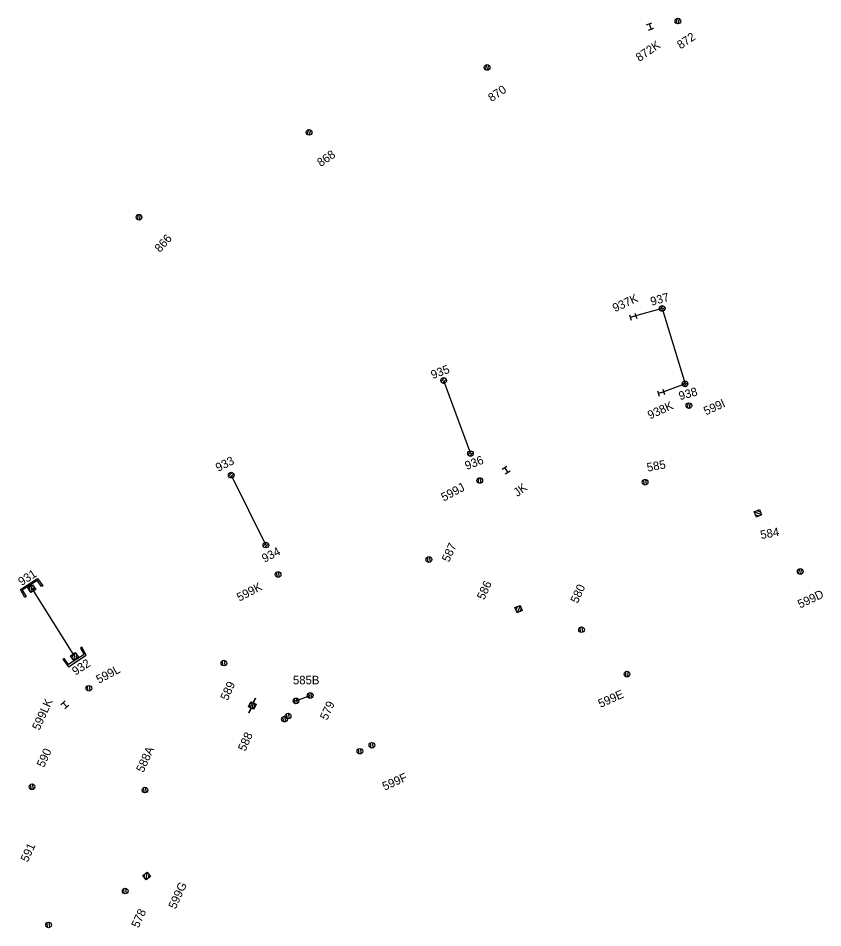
# Model space of a CAD drawing. Extents: x -595867 to -593796, y -1159595 to -1157495.
# Drawn here: x -594550.3 to -594408.1, y -1157774.7 to -1157614 of the extents above; entities that cross this region are included whole.
import ezdxf

# ---------------------------------------------------------------- set-up
doc = ezdxf.new("R2010")
doc.units = 0
for name, color, linetype in [('BVK_kanalizace_jednotna_nova', 7, 'Continuous'), ('SO31_06_54_1-protlak', 7, 'Continuous'), ('Teplarny Horkovod', 7, 'Continuous')]:
    doc.layers.add(name, color=color, linetype=linetype)

# ---------------------------------------------------------------- blocks, each defined once
blk = doc.blocks.new('C661_1')
at = {"layer": 'SO31_06_54_1-protlak'}
for p, q in [((-0.005, 0.0003), (-0.0003, 0.005)), ((-0.005, -0.005), (0.005, 0.005)), ((0.0003, -0.005), (0.005, -0.0003))]:
    blk.add_line(p, q, dxfattribs=at)
blk.add_lwpolyline([(-0.005, 0.005), (0.005, 0.005), (0.005, -0.005), (-0.005, -0.005)], close=True, dxfattribs=at)
blk.add_lwpolyline([(-0.005, 0.005), (0.005, 0.005), (0.005, -0.005), (-0.005, -0.005), (-0.005, 0.005)], dxfattribs=at)
blk = doc.blocks.new('C666')
at = {"layer": 'SO31_06_54_1-protlak'}
for p, q in [((-0.005, 0.0001), (-0.0001, 0.005)), ((-0.0048, -0.005), (0.005, 0.0048)), ((0.0049, 0), (0.015, 0)), ((-0.005, 0), (-0.015, 0)), ((0.0005, -0.005), (0.005, -0.0005))]:
    blk.add_line(p, q, dxfattribs=at)
blk.add_lwpolyline([(-0.005, 0.005), (0.005, 0.005), (0.005, -0.005), (-0.005, -0.005)], close=True, dxfattribs=at)
blk.add_lwpolyline([(-0.005, 0.005), (0.005, 0.005), (0.005, -0.005), (-0.005, -0.005), (-0.005, 0.005)], dxfattribs=at)
blk = doc.blocks.new('C661_3')
at = {"layer": 'Teplarny Horkovod'}
for p, q in [((-0.5, 0.03), (-0.03, 0.5)), ((-0.5, -0.5), (0.5, 0.5)), ((0.03, -0.5), (0.5, -0.03))]:
    blk.add_line(p, q, dxfattribs=at)
blk.add_lwpolyline([(-0.5, 0.5), (0.5, 0.5), (0.5, -0.5), (-0.5, -0.5)], close=True, dxfattribs=at)
blk.add_lwpolyline([(-0.5, 0.5), (0.5, 0.5), (0.5, -0.5), (-0.5, -0.5), (-0.5, 0.5)], dxfattribs=at)
blk = doc.blocks.new('C725')
at = {"layer": 'Teplarny Horkovod'}
for p, q in [((-0.46, -0.18), (0.18, 0.46)), ((-0.2, -0.45), (0.45, 0.2))]:
    blk.add_line(p, q, dxfattribs=at)
blk.add_circle((0, 0), 0.5, dxfattribs=at)
blk = doc.blocks.new('C662')
at = {"layer": 'Teplarny Horkovod'}
for p, q in [((-0.5, 0.5), (0.5, 0.5)), ((0, 0.5), (0, -0.5)), ((-0.5, -0.5), (0.5, -0.5))]:
    blk.add_line(p, q, dxfattribs=at)

msp = doc.modelspace()

# ---------------------------------------------------------------- linework, layer by layer
at = {"layer": 'BVK_kanalizace_jednotna_nova'}
for p, q in [((-594439.28, -1157615.19), (-594438.34, -1157614.83)), ((-594434.04, -1157614.89), (-594433.79, -1157614.02)), ((-594433.69, -1157615.01), (-594433.43, -1157614.11)), ((-594438.92, -1157616.13), (-594437.98, -1157615.77)), ((-594438.81, -1157615.01), (-594438.45, -1157615.95)), ((-594467.76, -1157623.08), (-594467.51, -1157622.21)), ((-594467.41, -1157623.2), (-594467.15, -1157622.3)), ((-594499.23, -1157634.55), (-594498.98, -1157633.68)), ((-594498.88, -1157634.67), (-594498.62, -1157633.77)), ((-594529.18, -1157649.61), (-594529.15, -1157648.7)), ((-594528.81, -1157649.63), (-594528.78, -1157648.7)), ((-594432.1, -1157682.82), (-594431.85, -1157681.95)), ((-594431.75, -1157682.94), (-594431.49, -1157682.04)), ((-594464.78, -1157693.65), (-594463.94, -1157693.11)), ((-594464.36, -1157693.38), (-594463.82, -1157694.22)), ((-594468.96, -1157696.11), (-594468.93, -1157695.2)), ((-594468.58, -1157696.13), (-594468.56, -1157695.2)), ((-594464.24, -1157694.49), (-594463.4, -1157693.95)), ((-594439.64, -1157696.45), (-594439.8, -1157695.55)), ((-594439.27, -1157696.39), (-594439.43, -1157695.48)), ((-594418.95, -1157701.73), (-594420.25, -1157701.21)), ((-594419.43, -1157701.94), (-594420.05, -1157701.7)), ((-594419.15, -1157701.25), (-594419.77, -1157701)), ((-594477.85, -1157710.11), (-594478.01, -1157709.21)), ((-594477.48, -1157710.05), (-594477.65, -1157709.14)), ((-594412.42, -1157712.12), (-594412.17, -1157711.25)), ((-594412.07, -1157712.24), (-594411.81, -1157711.34)), ((-594504.5, -1157712.76), (-594504.66, -1157711.86)), ((-594504.13, -1157712.71), (-594504.3, -1157711.79)), ((-594450.88, -1157722.49), (-594451.04, -1157721.59)), ((-594450.51, -1157722.44), (-594450.67, -1157721.52)), ((-594513.72, -1157728.32), (-594513.88, -1157727.41)), ((-594514.09, -1157728.38), (-594514.25, -1157727.48)), ((-594442.95, -1157730.3), (-594442.92, -1157729.39)), ((-594442.58, -1157730.32), (-594442.55, -1157729.39)), ((-594537.95, -1157732.84), (-594538.11, -1157731.94)), ((-594537.58, -1157732.78), (-594537.74, -1157731.87)), ((-594501.24, -1157734.58), (-594498.72, -1157733.63)), ((-594498.83, -1157734.11), (-594498.99, -1157733.21)), ((-594498.46, -1157734.05), (-594498.62, -1157733.14)), ((-594542.77, -1157735.27), (-594542.04, -1157734.58)), ((-594542.4, -1157734.93), (-594541.72, -1157735.65)), ((-594542.08, -1157736), (-594541.35, -1157735.31)), ((-594501.35, -1157735.06), (-594501.51, -1157734.16)), ((-594500.98, -1157735), (-594501.14, -1157734.09)), ((-594502.74, -1157737.74), (-594502.9, -1157736.84)), ((-594502.37, -1157737.69), (-594502.54, -1157736.77)), ((-594503.38, -1157738.28), (-594503.54, -1157737.38)), ((-594503.01, -1157738.23), (-594503.18, -1157737.31)), ((-594490.05, -1157743.97), (-594490.21, -1157743.07)), ((-594489.68, -1157743.91), (-594489.84, -1157743)), ((-594487.92, -1157742.91), (-594488.08, -1157742.01)), ((-594487.55, -1157742.85), (-594487.71, -1157741.94)), ((-594547.99, -1157750.23), (-594548.15, -1157749.33)), ((-594547.62, -1157750.18), (-594547.79, -1157749.26)), ((-594528.03, -1157750.81), (-594528.19, -1157749.91)), ((-594527.66, -1157750.75), (-594527.82, -1157749.84)), ((-594528.04, -1157765.78), (-594527.95, -1157765.13)), ((-594527.72, -1157766.21), (-594527.53, -1157764.81)), ((-594527.3, -1157765.89), (-594527.21, -1157765.23)), ((-594531.53, -1157768.64), (-594531.69, -1157767.74)), ((-594531.16, -1157768.58), (-594531.32, -1157767.67)), ((-594545.08, -1157774.64), (-594545.24, -1157773.74)), ((-594544.71, -1157774.58), (-594544.87, -1157773.67))]:
    msp.add_line(p, q, dxfattribs=at)
for points in [[(-594419.86, -1157702.13), (-594420.26, -1157701.21), (-594419.34, -1157700.81), (-594418.94, -1157701.73)], [(-594528.32, -1157765.41), (-594527.53, -1157764.81), (-594526.92, -1157765.6), (-594527.72, -1157766.21)]]:
    msp.add_lwpolyline(points, close=True, dxfattribs=at)
for points in [[(-594419.86, -1157702.13), (-594420.26, -1157701.21), (-594419.34, -1157700.81), (-594418.94, -1157701.73), (-594419.86, -1157702.13)], [(-594528.32, -1157765.41), (-594527.53, -1157764.81), (-594526.92, -1157765.6), (-594527.72, -1157766.21), (-594528.32, -1157765.41)]]:
    msp.add_lwpolyline(points, dxfattribs=at)
for centre in [(-594433.73, -1157614.51), (-594433.73, -1157614.51), (-594467.45, -1157622.7), (-594467.45, -1157622.7), (-594498.92, -1157634.17), (-594498.92, -1157634.17), (-594528.97, -1157649.16), (-594528.97, -1157649.16), (-594431.79, -1157682.44), (-594431.79, -1157682.44), (-594468.75, -1157695.66), (-594468.75, -1157695.66), (-594439.53, -1157695.97), (-594439.53, -1157695.97), (-594477.74, -1157709.63), (-594477.74, -1157709.63), (-594412.11, -1157711.74), (-594412.11, -1157711.74), (-594504.39, -1157712.28), (-594504.39, -1157712.28), (-594450.77, -1157722.01), (-594450.77, -1157722.01), (-594513.98, -1157727.9), (-594513.98, -1157727.9), (-594442.74, -1157729.85), (-594442.74, -1157729.85), (-594537.84, -1157732.36), (-594537.84, -1157732.36), (-594498.72, -1157733.63), (-594498.72, -1157733.63), (-594501.24, -1157734.58), (-594501.24, -1157734.58), (-594502.63, -1157737.26), (-594502.63, -1157737.26), (-594503.27, -1157737.8), (-594503.27, -1157737.8), (-594489.94, -1157743.49), (-594489.94, -1157743.49), (-594487.81, -1157742.43), (-594487.81, -1157742.43), (-594547.88, -1157749.75), (-594547.88, -1157749.75), (-594527.92, -1157750.33), (-594527.92, -1157750.33), (-594531.42, -1157768.16), (-594531.42, -1157768.16), (-594544.97, -1157774.16), (-594544.97, -1157774.16)]:
    msp.add_circle(centre, 0.5, dxfattribs=at)
at = {"layer": 'Teplarny Horkovod'}
for p, q in [((-594436.51, -1157665.27), (-594441.65, -1157666.71)), ((-594436.51, -1157665.27), (-594432.47, -1157678.59)), ((-594475.14, -1157678.01), (-594470.39, -1157690.92)), ((-594432.47, -1157678.59), (-594436.72, -1157680.16)), ((-594512.68, -1157694.7), (-594506.55, -1157707.06)), ((-594547.93, -1157714.76), (-594540.38, -1157726.75))]:
    msp.add_line(p, q, dxfattribs=at)
for points in [[(-594549.13, -1157716.32), (-594549.94, -1157714.91), (-594546.93, -1157712.97), (-594545.96, -1157714.26), (-594546.18, -1157714.39), (-594547, -1157713.31), (-594549.63, -1157715), (-594548.92, -1157716.17)], [(-594542.46, -1157727.24), (-594541.46, -1157728.56), (-594538.31, -1157726.53), (-594539.07, -1157725.12), (-594539.32, -1157725.28), (-594538.68, -1157726.4), (-594541.42, -1157728.15), (-594542.2, -1157727.09)]]:
    msp.add_lwpolyline(points, close=True, dxfattribs=at)

# ---------------------------------------------------------------- block references
at = {"layer": 'BVK_kanalizace_jednotna_nova'}
for name, p, xscale, yscale, rotation in [('C661_1', (-594461.89, -1157718.38), 99.99962148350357, 99.99962148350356, -156.9789585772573), ('C666', (-594508.99, -1157735.39), 99.99954864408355, 99.99954864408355, 65.78237621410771), ('C666', (-594508.95, -1157735.41), 99.99954864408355, 99.99954864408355, 65.78237621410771)]:
    msp.add_blockref(name, p, dxfattribs=dict(at, xscale=xscale, yscale=yscale, rotation=rotation))
at = {"layer": 'Teplarny Horkovod'}
for p in [(-594436.51, -1157665.27), (-594475.14, -1157678.01), (-594432.47, -1157678.59), (-594470.39, -1157690.92), (-594512.68, -1157694.7), (-594506.55, -1157707.06)]:
    msp.add_blockref('C725', p, dxfattribs=at)
for name, p, xscale, yscale, rotation in [('C662', (-594441.65, -1157666.71), 0.9999993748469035, 0.9999993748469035, -72.35529582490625), ('C662', (-594436.72, -1157680.16), 1.000002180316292, 1.0000021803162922, -71.49257649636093), ('C661_3', (-594547.93, -1157714.76), 1.0000007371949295, 1.0000007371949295, 33.355371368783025), ('C661_3', (-594540.38, -1157726.75), 1.0000048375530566, 1.0000048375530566, 34.396175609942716)]:
    msp.add_blockref(name, p, dxfattribs=dict(at, xscale=xscale, yscale=yscale, rotation=rotation))

# ---------------------------------------------------------------- texts
at = {"layer": 'BVK_kanalizace_jednotna_nova'}
for s, rotation, p in [('872', 34.56, (-594433.25, -1157619.54)), ('872K', 34.56, (-594440.55, -1157621.75)), ('870', 34.56, (-594466.65, -1157628.86)), ('868', 34.56, (-594496.87, -1157640.32)), ('866', 48.37, (-594525.27, -1157655.48)), ('937K', 24.7, (-594444.87, -1157665.96)), ('938K', 24.7, (-594438.67, -1157684.89)), ('599I', 24.1252, (-594428.78, -1157684.17)), ('585', 10.5999, (-594439.08, -1157694.11)), ('599J', 27.9969, (-594475.1, -1157699.39)), ('JK', 37.23, (-594462.09, -1157698.6)), ('584', 10.5999, (-594419.03, -1157706.02)), ('587', 65.5984, (-594474.18, -1157710.19)), ('599K', 27.9969, (-594511.21, -1157717.08)), ('586', 65.5984, (-594467.97, -1157716.86)), ('580', 65.5984, (-594451.44, -1157717.47)), ('599D', 25.28, (-594412.14, -1157718.28)), ('599L', 27.9969, (-594536.07, -1157731.57)), ('589', 65.5984, (-594513.31, -1157734.63)), ('599E', 24.1252, (-594447.42, -1157735.84)), ('599LK', 65.5984, (-594546.59, -1157739.89)), ('579', 65.5984, (-594495.72, -1157738.1)), ('588', 65.5984, (-594510.2, -1157743.59)), ('590', 65.5984, (-594545.77, -1157746.45)), ('588A', 65.5984, (-594528.2, -1157747.34)), ('599F', 24.1252, (-594485.57, -1157750.46)), ('591', 65.5984, (-594548.63, -1157763.17)), ('599G', 65.5984, (-594522.5, -1157771.47)), ('578', 65.5984, (-594529.05, -1157774.8))]:
    msp.add_text(s, height=1.5, rotation=rotation, dxfattribs=at).set_placement(p)
msp.add_text('585B', height=1.5, dxfattribs=at).set_placement((-594501.77, -1157731.65))
at = {"layer": 'Teplarny Horkovod'}
for s, rotation, p in [('937', 15.5097, (-594438.37, -1157664.81)), ('935', 20.8817, (-594477.06, -1157677.77)), ('938', 15.5097, (-594433.37, -1157681.49)), ('933', 26.7726, (-594514.98, -1157694.15)), ('936', 20.8817, (-594471.05, -1157693.81)), ('934', 27.5417, (-594506.8, -1157710.2)), ('931', 32.8045, (-594549.73, -1157714.32)), ('932', 32.8045, (-594540.22, -1157730.14))]:
    msp.add_text(s, height=1.5, rotation=rotation, dxfattribs=at).set_placement(p)

doc.saveas('drawing.dxf')
